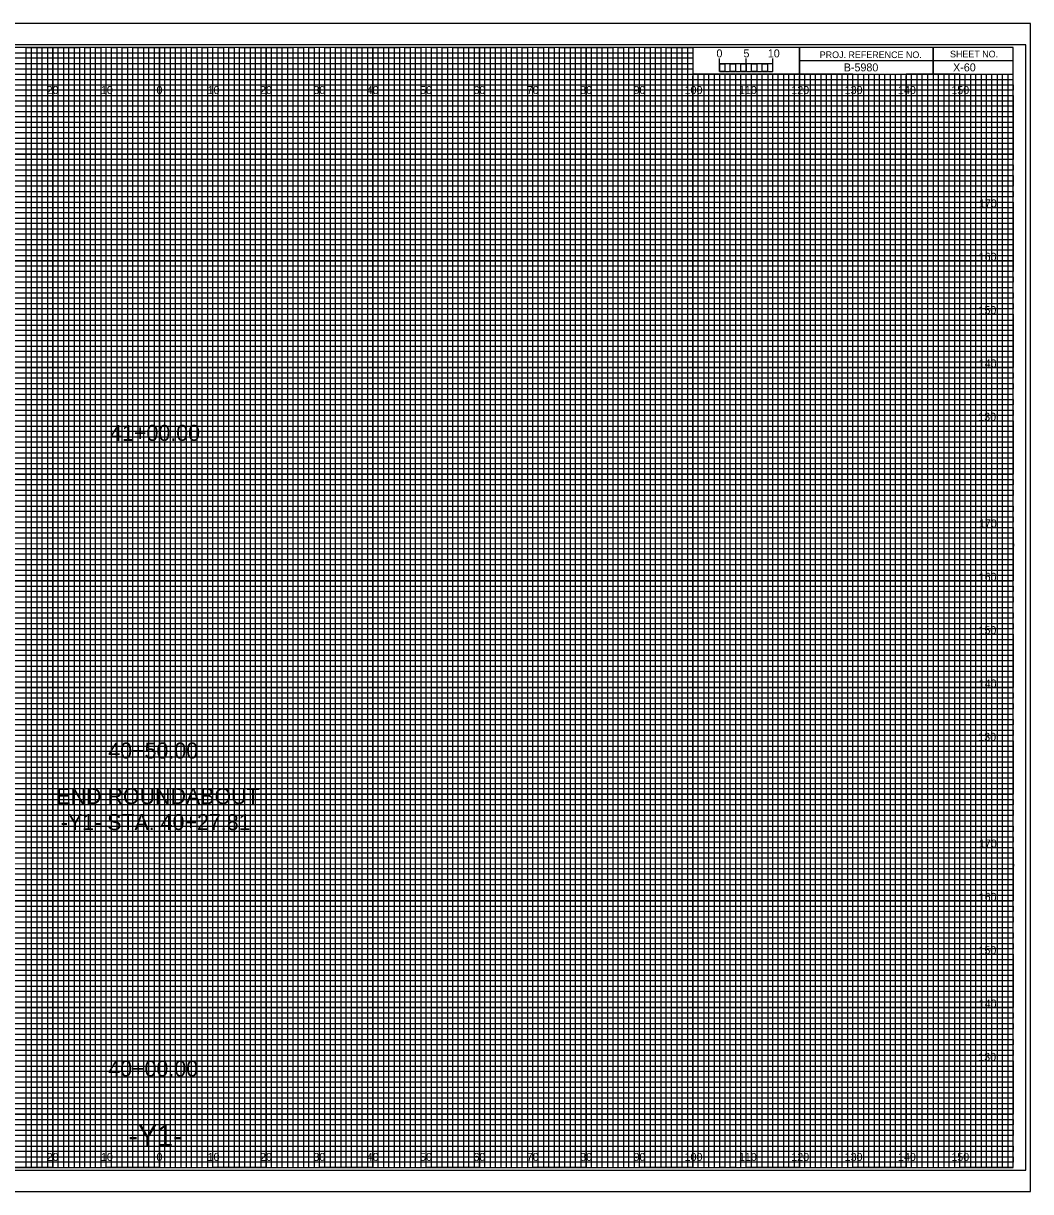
# Model space of a CAD drawing. Extents: x -13 to 323, y -5 to 4834.
# Drawn here: x 134.5 to 323.3, y 3075.5 to 3294.5 of the extents above; entities that cross this region are included whole.
import ezdxf

# ---------------------------------------------------------------- set-up
doc = ezdxf.new("R2010")
doc.units = 0
for name, color, linetype in [('Exist CMT Pavement', 7, 'Continuous'), ('Exist Cross Section Cell', 7, 'Continuous'), ('Exist XS Center Line Elevation Label', 7, 'Continuous'), ('Exist XS Ground Line', 7, 'Continuous'), ('Prop CMT Pvmt Course 1', 7, 'Continuous'), ('Prop CMT Pvmt Course 1 Wedge', 7, 'Continuous'), ('Prop CMT Pvmt Course 2', 7, 'Continuous'), ('Prop CMT Pvmt Course 2 Wedge', 7, 'Continuous'), ('Prop CMT Pvmt Course 3', 7, 'Continuous'), ('Prop CMT Pvmt Course 3 Wedge', 7, 'Continuous'), ('Prop CMT Pvmt Surface', 7, 'Continuous'), ('Prop CMT Pvmt Surface Shoulder', 7, 'Continuous'), ('Prop CMT Shld Paved Course 1', 7, 'Continuous'), ('Prop CMT Shld Paved Course 2', 7, 'Continuous'), ('Prop CMT Shld Paved Course 3', 7, 'Continuous'), ('Prop CMT Slope Grass', 7, 'Continuous'), ('Prop CMT Subgrade Earthwork', 7, 'Continuous')]:
    doc.layers.add(name, color=color, linetype=linetype)

msp = doc.modelspace()

# ---------------------------------------------------------------- linework, layer by layer
at = {"layer": 'Exist XS Center Line Elevation Label'}
for points in [[(125, 3080), (135, 3080), (135, 3290), (145, 3290), (145, 3080), (155, 3080), (155, 3290), (165, 3290), (165, 3080), (175, 3080), (175, 3290), (185, 3290), (185, 3080), (195, 3080), (195, 3290), (205, 3290), (205, 3080), (215, 3080), (215, 3290), (225, 3290), (225, 3080), (235, 3080), (235, 3290), (245, 3290), (245, 3080), (255, 3080), (255, 3290), (259.93, 3290), (260, 3290), (260, 3285), (264.99, 3285), (264.99, 3080), (275, 3080), (275, 3285), (285, 3285), (285, 3080), (295, 3080), (295, 3285), (305, 3285), (305, 3080), (315, 3080), (315, 3285)], [(0, 3285), (275, 3285)], [(0, 3265), (320, 3265), (320, 3275), (0, 3275)], [(0, 3245), (320, 3245), (320, 3255), (0, 3255)], [(0, 3225), (320, 3225), (320, 3235), (0, 3235)], [(0, 3205), (320, 3205), (320, 3215), (0, 3215)], [(0, 3185), (320, 3185), (320, 3195), (0, 3195)], [(0, 3165), (320, 3165), (320, 3175), (0, 3175)], [(0, 3145), (320, 3145), (320, 3155), (0, 3155)], [(0, 3125), (320, 3125), (320, 3135), (0, 3135)], [(0, 3105), (320, 3105), (320, 3115), (0, 3115)], [(0, 3085), (320, 3085), (320, 3095), (0, 3095)]]:
    msp.add_lwpolyline(points, dxfattribs=at)
at = {"layer": 'Exist XS Ground Line'}
for p, q in [((150, 3290), (140, 3290)), ((140, 3290), (140, 3080)), ((150, 3080), (150, 3290)), ((170, 3290), (160, 3290)), ((160, 3290), (160, 3080)), ((170, 3080), (170, 3290)), ((190, 3290), (180, 3290)), ((180, 3290), (180, 3080)), ((190, 3080), (190, 3290)), ((210, 3290), (200, 3290)), ((200, 3290), (200, 3080)), ((210, 3080), (210, 3290)), ((230, 3290), (220, 3290)), ((220, 3290), (220, 3080)), ((230, 3080), (230, 3290)), ((250, 3290), (240, 3290)), ((240, 3290), (240, 3080)), ((250, 3080), (250, 3290)), ((260, 3290), (260, 3080)), ((270, 3080), (270, 3285)), ((290, 3285), (280, 3285)), ((280, 3285), (280, 3080)), ((290, 3080), (290, 3285)), ((310, 3285), (300, 3285)), ((300, 3285), (300, 3080)), ((310, 3080), (310, 3285)), ((140, 3080), (130, 3080)), ((160, 3080), (150, 3080)), ((180, 3080), (170, 3080)), ((200, 3080), (190, 3080)), ((220, 3080), (210, 3080)), ((240, 3080), (230, 3080)), ((260, 3080), (250, 3080)), ((280, 3080), (270, 3080)), ((300, 3080), (290, 3080)), ((320, 3080), (310, 3080)), ((320, 3080), (320, 3080))]:
    msp.add_line(p, q, dxfattribs=at)
for points in [[(0, 3280), (320, 3280), (320, 3270), (0, 3270)], [(0, 3260), (320, 3260), (320, 3250), (0, 3250)], [(0, 3240), (320, 3240), (320, 3230), (0, 3230)], [(0, 3220), (320, 3220), (320, 3210), (0, 3210)], [(0, 3200), (320, 3200), (320, 3190), (0, 3190)], [(0, 3180), (320, 3180), (320, 3170), (0, 3170)], [(0, 3160), (320, 3160), (320, 3150), (0, 3150)], [(0, 3140), (320, 3140), (320, 3130), (0, 3130)], [(0, 3120), (320, 3120), (320, 3110), (0, 3110)], [(0, 3100), (320, 3100), (320, 3090), (0, 3090)]]:
    msp.add_lwpolyline(points, dxfattribs=at)
at = {"layer": 'Prop CMT Pvmt Course 1'}
for p, q in [((267, 3285), (266.01, 3285)), ((266.01, 3285), (266.01, 3080)), ((267, 3080), (267, 3285)), ((269, 3285), (268, 3285)), ((268, 3285), (268, 3080)), ((269, 3080), (269, 3285)), ((266.01, 3080), (265, 3080)), ((268, 3080), (267, 3080))]:
    msp.add_line(p, q, dxfattribs=at)
for points in [[(135, 3080), (136, 3080), (136, 3290), (137, 3290), (137, 3080)], [(137, 3080), (138, 3080), (138, 3290), (139, 3290), (139, 3080)], [(140, 3080), (141, 3080), (141, 3290), (142, 3290), (142, 3080)], [(142, 3080), (143, 3080), (143, 3290), (144, 3290), (144, 3080)], [(145, 3080), (146, 3080), (146, 3290), (147, 3290), (147, 3080)], [(147, 3080), (148, 3080), (148, 3290), (149, 3290), (149, 3080)], [(150, 3080), (151, 3080), (151, 3290), (152, 3290), (152, 3080)], [(152, 3080), (153, 3080), (153, 3290), (154, 3290), (154, 3080)], [(155, 3080), (156, 3080), (156, 3290), (157, 3290), (157, 3080)], [(157, 3080), (158, 3080), (158, 3290), (159, 3290), (159, 3080)], [(160, 3080), (161, 3080), (161, 3290), (162, 3290), (162, 3080)], [(162, 3080), (163, 3080), (163, 3290), (164, 3290), (164, 3080)], [(165, 3080), (166, 3080), (166, 3290), (167, 3290), (167, 3080)], [(167, 3080), (168, 3080), (168, 3290), (169, 3290), (169, 3080)], [(170, 3080), (171, 3080), (171, 3290), (172, 3290), (172, 3080)], [(172, 3080), (173, 3080), (173, 3290), (174, 3290), (174, 3080)], [(175, 3080), (176, 3080), (176, 3290), (177, 3290), (177, 3080)], [(177, 3080), (178, 3080), (178, 3290), (179, 3290), (179, 3080)], [(180, 3080), (181, 3080), (181, 3290), (182, 3290), (182, 3080)], [(182, 3080), (183, 3080), (183, 3290), (184, 3290), (184, 3080)], [(185, 3080), (186, 3080), (186, 3290), (187, 3290), (187, 3080)], [(187, 3080), (188, 3080), (188, 3290), (189, 3290), (189, 3080)], [(190, 3080), (191, 3080), (191, 3290), (192, 3290), (192, 3080)], [(192, 3080), (193, 3080), (193, 3290), (194, 3290), (194, 3080)], [(195, 3080), (196, 3080), (196, 3290), (197, 3290), (197, 3080)], [(197, 3080), (198, 3080), (198, 3290), (199, 3290), (199, 3080)], [(200, 3080), (201, 3080), (201, 3290), (202, 3290), (202, 3080)], [(202, 3080), (203, 3080), (203, 3290), (204, 3290), (204, 3080)], [(205, 3080), (206, 3080), (206, 3290), (207, 3290), (207, 3080)], [(207, 3080), (208, 3080), (208, 3290), (209, 3290), (209, 3080)], [(210, 3080), (211, 3080), (211, 3290), (212, 3290), (212, 3080)], [(212, 3080), (213, 3080), (213, 3290), (214, 3290), (214, 3080)], [(215, 3080), (216, 3080), (216, 3290), (217, 3290), (217, 3080)], [(217, 3080), (218, 3080), (218, 3290), (219, 3290), (219, 3080)], [(220, 3080), (221, 3080), (221, 3290), (222, 3290), (222, 3080)], [(222, 3080), (223, 3080), (223, 3290), (224, 3290), (224, 3080)], [(225, 3080), (226, 3080), (226, 3290), (227, 3290), (227, 3080)], [(227, 3080), (228, 3080), (228, 3290), (229, 3290), (229, 3080)], [(230, 3080), (231, 3080), (231, 3290), (232, 3290), (232, 3080)], [(232, 3080), (233, 3080), (233, 3290), (234, 3290), (234, 3080)], [(235, 3080), (236, 3080), (236, 3290), (237, 3290), (237, 3080)], [(237, 3080), (238, 3080), (238, 3290), (239, 3290), (239, 3080)], [(240, 3080), (241, 3080), (241, 3290), (242, 3290), (242, 3080)], [(242, 3080), (243, 3080), (243, 3290), (244, 3290), (244, 3080)], [(245, 3080), (246, 3080), (246, 3290), (247, 3290), (247, 3080)], [(247, 3080), (248, 3080), (248, 3290), (249, 3290), (249, 3080)], [(250, 3080), (251, 3080), (251, 3290), (252, 3290), (252, 3080)], [(252, 3080), (253, 3080), (253, 3290), (254, 3290), (254, 3080)], [(255, 3080), (256, 3080), (256, 3290), (257, 3290), (257, 3080)], [(257, 3080), (258, 3080), (258, 3290), (259, 3290), (259, 3080)], [(260, 3080), (261, 3080), (261, 3285), (262.02, 3285), (262.02, 3080)], [(262, 3080), (263, 3080), (263, 3285), (263.99, 3285), (263.99, 3080)], [(270, 3080), (270.98, 3080), (270.98, 3285), (272, 3285), (272, 3080)], [(272, 3080), (273, 3080), (273, 3285), (274.05, 3285), (274.05, 3080)], [(275, 3080), (276, 3080), (276, 3285), (277, 3285), (277, 3080)], [(277, 3080), (278, 3080), (278, 3285), (279, 3285), (279, 3080)], [(280, 3080), (281, 3080), (281, 3285), (282, 3285), (282, 3080)], [(282, 3080), (283, 3080), (283, 3285), (284, 3285), (284, 3080)], [(285, 3080), (286, 3080), (286, 3285), (287, 3285), (287, 3080)], [(287, 3080), (288, 3080), (288, 3285), (289, 3285), (289, 3080)], [(290, 3080), (291, 3080), (291, 3285), (292, 3285), (292, 3080)], [(292, 3080), (293, 3080), (293, 3285), (294, 3285), (294, 3080)], [(295, 3080), (296, 3080), (296, 3285), (297, 3285), (297, 3080)], [(297, 3080), (298, 3080), (298, 3285), (299, 3285), (299, 3080)], [(300, 3080), (301, 3080), (301, 3285), (302, 3285), (302, 3080)], [(302, 3080), (303, 3080), (303, 3285), (304, 3285), (304, 3080)], [(305, 3080), (306, 3080), (306, 3285), (307, 3285), (307, 3080)], [(307, 3080), (308, 3080), (308, 3285), (309, 3285), (309, 3080)], [(310, 3080), (311, 3080), (311, 3285), (312, 3285), (312, 3080)], [(312, 3080), (313, 3080), (313, 3285), (314, 3285), (314, 3080)], [(315, 3080), (316, 3080), (316, 3285), (317, 3285), (317, 3080)], [(317, 3080), (318, 3080), (318, 3285), (319, 3285), (319, 3080)]]:
    msp.add_lwpolyline(points, dxfattribs=at)
at = {"layer": 'Prop CMT Pvmt Course 2'}
for p, q in [((323.3, 3294.5), (-13.4, 3294.5)), ((-13.4, 3075.5), (323.3, 3075.5))]:
    msp.add_line(p, q, dxfattribs=at)
at = {"layer": 'Prop CMT Pvmt Surface Shoulder'}
for p, q in [((305, 3290), (305, 3285)), ((305, 3285), (305, 3290)), ((280, 3287.5), (280, 3285)), ((320, 3287.49), (280, 3287.49)), ((280, 3285), (320, 3285))]:
    msp.add_line(p, q, dxfattribs=at)
for points in [[(320, 3290), (0, 3290), (0, 3080), (320, 3080)], [(280, 3290), (260, 3290), (260, 3285.03), (280, 3285.03)], [(320, 3290), (280, 3290), (280, 3285), (320, 3285)]]:
    msp.add_lwpolyline(points, close=True, dxfattribs=at)
at = {"layer": 'Prop CMT Shld Paved Course 1'}
msp.add_lwpolyline([(-13.4, 3075.5), (323.3, 3075.5), (323.3, 3294.5), (-13.4, 3294.5)], close=True, dxfattribs=at)
at = {"layer": 'Prop CMT Shld Paved Course 2'}
msp.add_lwpolyline([(-10.8, 3079.5), (322.4, 3079.5), (322.4, 3290.5), (-10.8, 3290.5)], close=True, dxfattribs=at)
at = {"layer": 'Prop CMT Shld Paved Course 3'}
for p, q in [((140, 3080), (140, 3290)), ((150, 3080), (150, 3290)), ((160, 3080), (160, 3290)), ((170, 3080), (170, 3290)), ((180, 3080), (180, 3290)), ((190, 3080), (190, 3290)), ((200, 3080), (200, 3290)), ((210, 3080), (210, 3290)), ((220, 3080), (220, 3290)), ((230, 3080), (230, 3290)), ((240, 3080), (240, 3290)), ((250, 3080), (250, 3290)), ((260, 3080), (260, 3284.69)), ((270, 3080), (270, 3284.69)), ((280, 3080), (280, 3284.69)), ((290, 3080), (290, 3284.69)), ((300, 3080), (300, 3284.69)), ((310, 3080), (310, 3284.69)), ((0, 3280), (320, 3280)), ((0, 3270), (320, 3270)), ((0, 3260), (320, 3260)), ((0, 3250), (320, 3250)), ((0, 3240), (320, 3240)), ((0, 3230), (320, 3230)), ((0, 3220), (320, 3220)), ((0, 3210), (320, 3210)), ((0, 3200), (320, 3200)), ((0, 3190), (320, 3190)), ((0, 3180), (320, 3180)), ((0, 3170), (320, 3170)), ((0, 3160), (320, 3160)), ((0, 3150), (320, 3150)), ((0, 3140), (320, 3140)), ((0, 3130), (320, 3130)), ((0, 3120), (320, 3120)), ((0, 3110), (320, 3110)), ((0, 3100), (320, 3100)), ((0, 3090), (320, 3090))]:
    msp.add_line(p, q, dxfattribs=at)
at = {"layer": 'Prop CMT Slope Grass'}
for p, q in [((0, 3289), (260, 3289)), ((260, 3287.98), (0, 3287.98)), ((260, 3289), (260, 3287.98)), ((0, 3287), (260, 3287)), ((260, 3285.89), (0, 3285.89)), ((260, 3287), (260, 3285.89)), ((0, 3284), (320, 3284))]:
    msp.add_line(p, q, dxfattribs=at)
for points in [[(0, 3283), (270, 3283), (320, 3283), (320, 3282), (0, 3282)], [(0, 3281), (320, 3281), (320, 3279), (0, 3279)], [(0, 3278), (320, 3278), (320, 3277), (0, 3276.98)], [(0, 3276), (320, 3276), (320, 3274), (0, 3274)], [(0, 3273), (320, 3273), (320, 3272), (0, 3272)], [(0, 3271), (320, 3271), (320, 3269), (0, 3269)], [(0, 3268), (320, 3268), (320, 3267), (0, 3267)], [(0, 3266), (320, 3266), (320, 3264), (0, 3264)], [(0, 3263), (320, 3263), (320, 3262), (0, 3262)], [(0, 3261), (320, 3261), (320, 3259), (0, 3259)], [(0, 3258), (320, 3258), (320, 3257), (0, 3257)], [(0, 3256), (320, 3256), (320, 3253.95), (320, 3253), (320, 3252), (0, 3252)], [(0, 3254), (320, 3254), (320, 3253), (0, 3253)], [(0, 3251), (320, 3251), (320, 3249), (0, 3249.03)], [(0, 3249.03), (320, 3249), (320, 3248), (0, 3248)], [(0, 3247), (320, 3247), (320, 3246), (0, 3246)], [(0, 3244), (320, 3244), (320, 3243), (0, 3243)], [(0, 3242), (320, 3242), (320, 3241), (0, 3241)], [(-0.07, 3238.89), (320, 3238.89), (320, 3237.88), (-0.07, 3237.88)], [(0, 3237), (320, 3237), (320, 3236), (0, 3236)], [(0, 3234), (320, 3234), (320, 3233), (0, 3233)], [(0, 3232), (320, 3232), (320, 3231), (0, 3231)], [(0, 3229), (320, 3229), (320, 3228), (0, 3228)], [(0, 3227), (320, 3227), (320, 3226), (0, 3226)], [(0, 3224), (320, 3224), (320, 3223), (0, 3223)], [(0, 3222), (320, 3222), (320, 3221), (0, 3221)], [(0, 3219), (320, 3219), (319.99, 3217.98), (0, 3218)], [(0, 3217), (320, 3217), (320, 3216), (0, 3216)], [(0, 3214), (320, 3214), (320, 3213), (0, 3213)], [(0, 3212), (320, 3212), (320, 3211), (0, 3211)], [(0, 3209), (320, 3209), (320, 3208), (0, 3208)], [(0, 3207), (320, 3207), (320, 3206), (0, 3206)], [(0, 3204), (320, 3204), (320, 3203), (0, 3203)], [(0, 3202), (320, 3202), (320, 3201), (0, 3201)], [(0, 3199), (320, 3199), (320, 3198), (0, 3198)], [(0, 3196.99), (320.07, 3196.91), (320, 3196), (0, 3196)], [(0, 3194), (320, 3194), (320, 3193), (0, 3193)], [(0, 3192), (320, 3192), (320, 3191), (0, 3191)], [(0, 3189), (320, 3189), (320, 3188), (0, 3188)], [(0, 3187), (320, 3187), (320, 3186), (0, 3186)], [(0, 3184), (320, 3184), (320, 3183), (0, 3183)], [(0, 3182), (320, 3182), (320, 3181), (0, 3181)], [(0, 3179), (320, 3179), (320, 3178), (0, 3178)], [(0, 3177), (320, 3177), (320, 3176), (0, 3176)], [(0, 3174), (320, 3174), (320, 3173), (0, 3173)], [(0, 3172), (320, 3172), (320, 3171), (0, 3171)], [(0, 3169), (320, 3169), (320, 3168), (0, 3168)], [(0, 3167), (320, 3167), (320, 3166), (0, 3166)], [(0, 3164), (320, 3164), (320, 3163), (0, 3163)], [(0, 3162), (320, 3162), (320, 3161), (0, 3161)], [(0, 3159), (320, 3159), (319.99, 3157.98), (0, 3158)], [(0, 3157), (320, 3157), (320, 3156), (0, 3156)], [(0, 3154), (320, 3154), (320, 3153), (0, 3153)], [(0, 3152), (320, 3152), (320, 3151), (0, 3151)], [(0, 3149), (320, 3149), (320, 3148), (0, 3148)], [(0, 3147), (320, 3147), (320, 3146), (0, 3146)], [(0, 3144), (320, 3144), (320, 3143), (0, 3143)], [(0, 3142), (320, 3142), (320, 3141), (0, 3141)], [(0, 3139), (320, 3139), (320, 3138), (0, 3138)], [(0, 3136.99), (320.07, 3136.91), (320, 3136), (0, 3136)], [(0, 3134), (320, 3134), (320, 3133), (0, 3133)], [(0, 3132), (320, 3132), (320, 3131), (0, 3131)], [(0, 3129), (320, 3129), (320, 3128), (0, 3128)], [(0, 3127), (320, 3127), (320, 3126), (0, 3126)], [(0, 3124), (320, 3124), (320, 3123), (0, 3123)], [(0, 3122), (320, 3122), (320, 3121), (0, 3121)], [(0, 3119), (320, 3119), (320, 3118), (0, 3118)], [(0, 3117), (320, 3117), (320, 3116), (0, 3116)], [(0, 3114), (320, 3114), (320, 3113), (0, 3113)], [(0, 3112), (320, 3112), (320, 3111), (0, 3111)], [(0, 3109), (320, 3109), (320, 3108), (0, 3108)], [(0, 3107), (320, 3107), (320, 3106), (0, 3106)], [(0, 3104), (320, 3104), (320, 3103), (0, 3103)], [(0, 3102), (320, 3102), (320, 3101), (0, 3101)], [(0, 3099), (320, 3099), (320, 3098), (0, 3098)], [(0, 3097), (320, 3097), (320, 3096), (0, 3096)], [(0, 3094), (320, 3094), (320, 3093), (0, 3093)], [(0, 3092), (320, 3092), (320, 3091), (0, 3091)], [(0, 3089), (320, 3089), (320, 3088), (0, 3088)], [(0, 3087), (320, 3087), (320, 3086), (0, 3086)], [(0, 3084), (320, 3084), (320, 3083), (0, 3083)], [(0, 3082), (320, 3082), (320, 3081), (0, 3081)]]:
    msp.add_lwpolyline(points, dxfattribs=at)
at = {"layer": 'Prop CMT Subgrade Earthwork'}
for p, q in [((265, 3285.49), (265, 3287.9)), ((265, 3286.9), (265, 3287.9)), ((270, 3285.49), (270, 3287.9)), ((275, 3285.49), (275, 3287.9)), ((275, 3286.9), (275, 3287.9))]:
    msp.add_line(p, q, dxfattribs=at)
for points in [[(275, 3286.9), (265, 3286.9), (265, 3285.49), (275, 3285.49)], [(265, 3286.9), (266, 3286.9), (266, 3285.49), (265, 3285.49)], [(267, 3286.9), (268, 3286.9), (268, 3285.49), (267, 3285.49)], [(269, 3286.9), (270, 3286.9), (270, 3285.49), (269, 3285.49)], [(271, 3286.9), (272, 3286.9), (272, 3285.49), (271, 3285.49)], [(273, 3286.9), (274, 3286.9), (274, 3285.49), (273, 3285.49)]]:
    msp.add_lwpolyline(points, close=True, dxfattribs=at)

# ---------------------------------------------------------------- texts
at = {"layer": 'Exist CMT Pavement'}
msp.add_text('-Y1-', height=4, dxfattribs=at).set_placement((154.21, 3084))
at = {"layer": 'Exist Cross Section Cell'}
for s, p in [('20', (138.86, 3281.25)), ('10', (149.04, 3281.25)), ('0', (159.45, 3281.25)), ('0', (159.45, 3281.25)), ('10', (169.04, 3281.25)), ('20', (178.86, 3281.25)), ('30', (188.86, 3281.25)), ('40', (198.86, 3281.25)), ('50', (208.86, 3281.25)), ('60', (218.86, 3281.25)), ('70', (228.86, 3281.25)), ('80', (238.86, 3281.25)), ('90', (248.86, 3281.25)), ('100', (258.44, 3281.25)), ('110', (268.62, 3281.25)), ('120', (278.44, 3281.25)), ('130', (288.44, 3281.25)), ('140', (298.44, 3281.25)), ('150', (308.44, 3281.25)), ('20', (138.86, 3081.25)), ('10', (149.04, 3081.25)), ('0', (159.45, 3081.25)), ('0', (159.45, 3081.25)), ('10', (169.04, 3081.25)), ('20', (178.86, 3081.25)), ('30', (188.86, 3081.25)), ('40', (198.86, 3081.25)), ('50', (208.86, 3081.25)), ('60', (218.86, 3081.25)), ('70', (228.86, 3081.25)), ('80', (238.86, 3081.25)), ('90', (248.86, 3081.25)), ('100', (258.44, 3081.25)), ('110', (268.62, 3081.25)), ('120', (278.44, 3081.25)), ('130', (288.44, 3081.25)), ('140', (298.44, 3081.25)), ('150', (308.44, 3081.25))]:
    msp.add_text(s, height=1.5, dxfattribs=at).set_placement(p)
at = {"layer": 'Prop CMT Pvmt Course 1 Wedge'}
for s, p in [('41+00.00', (150.77, 3216.23)), ('40+50.00', (150.41, 3156.69)), ('END ROUNDABOUT', (140.68, 3148.15)), ('-Y1- STA. 40+27.81', (141.51, 3143.27)), ('40+00.00', (150.41, 3097.08))]:
    msp.add_text(s, height=3, dxfattribs=at).set_placement(p)
at = {"layer": 'Prop CMT Pvmt Course 2 Wedge'}
msp.add_text('X-60', height=1.5, dxfattribs=at).set_placement((308.77, 3285.5))
at = {"layer": 'Prop CMT Pvmt Course 3'}
for s, p in [('170', (313.61, 3260)), ('160', (313.57, 3250)), ('150', (313.52, 3240)), ('140', (313.57, 3230)), ('130', (313.49, 3220)), ('170', (313.61, 3200)), ('160', (313.57, 3190)), ('150', (313.52, 3180)), ('140', (313.57, 3170)), ('130', (313.49, 3160)), ('170', (313.61, 3140)), ('160', (313.57, 3130)), ('150', (313.52, 3120)), ('140', (313.57, 3110)), ('130', (313.49, 3100))]:
    msp.add_text(s, height=1.5, dxfattribs=at).set_placement(p)
at = {"layer": 'Prop CMT Pvmt Course 3 Wedge'}
msp.add_text('B-5980', height=1.5, dxfattribs=at).set_placement((288.28, 3285.5))
at = {"layer": 'Prop CMT Pvmt Surface'}
for s, p in [('5', (269.47, 3288.12)), ('10', (274.04, 3288.12))]:
    msp.add_text(s, height=1.5, dxfattribs=at).set_placement(p)
at = {"layer": 'Prop CMT Pvmt Surface Shoulder'}
for s, p in [('SHEET NO.', (308.19, 3288.12)), ('PROJ. REFERENCE NO.', (283.77, 3287.99))]:
    msp.add_text(s, height=1.25, dxfattribs=at).set_placement(p)
at = {"layer": 'Prop CMT Subgrade Earthwork'}
msp.add_text('0', height=1.5, dxfattribs=at).set_placement((264.41, 3288.12))

doc.saveas('drawing.dxf')
